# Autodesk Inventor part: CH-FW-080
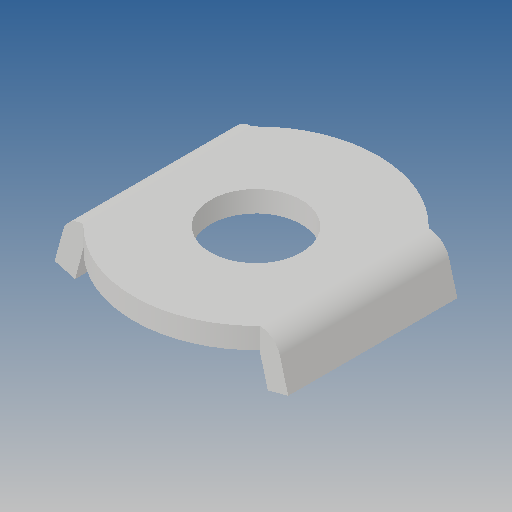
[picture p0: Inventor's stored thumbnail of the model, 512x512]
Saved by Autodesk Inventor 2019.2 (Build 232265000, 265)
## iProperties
Created: 2012-09
Part Number: CH-FW-080
Material: Ogólny
Document SubType Name: Modeling
Designer: CADENGINEERING4
Density: 1 g/cm^3
Appearance: Domyślna
Author: CADENGINEERING4
Revision Number: ÈÎºÎ
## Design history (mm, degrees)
feature "ÇÐ³ý-À­Éì6"
node "Bryła1"
